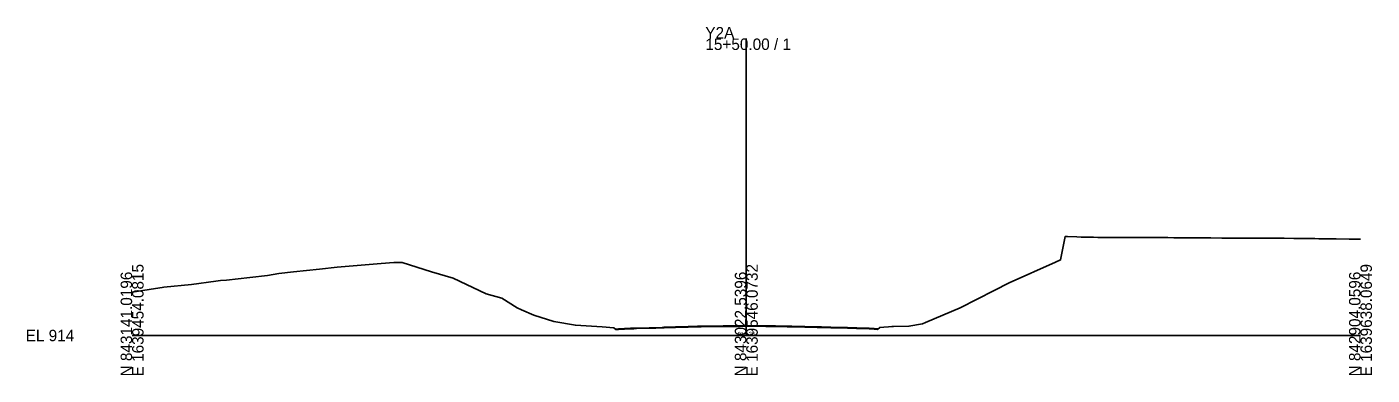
# Model space of a CAD drawing. Extents: x -26 to 303, y -10 to 10517.
# Drawn here: x -25.7 to 302.8, y 4990.3 to 5075.5 of the extents above; entities that cross this region are included whole.
import ezdxf

# ---------------------------------------------------------------- set-up
doc = ezdxf.new("R2010")
doc.units = 0
for name, color, linetype in [('Exist Cross Section Cell', 7, 'Continuous'), ('Exist XS Center Line Elevation Label', 7, 'Continuous'), ('Exist XS Ground Line', 7, 'Continuous'), ('Prop CMT Pvmt Surface Overlay', 7, 'Continuous')]:
    doc.layers.add(name, color=color, linetype=linetype)

msp = doc.modelspace()

# ---------------------------------------------------------------- linework, layer by layer
at = {"layer": 'Exist Cross Section Cell'}
for p, q in [((150, 5000), (150, 5072.63)), ((0, 5000), (150, 5000)), ((150, 5000), (300, 5000))]:
    msp.add_line(p, q, dxfattribs=at)
at = {"layer": 'Exist XS Ground Line'}
msp.add_lwpolyline([(0, 5010.63), (6.79, 5011.64), (7.34, 5011.73), (7.77, 5011.78), (14.47, 5012.51), (20.43, 5013.25), (21.59, 5013.42), (23.09, 5013.55), (28.72, 5014.2), (33.09, 5014.71), (35.85, 5015.15), (39.4, 5015.54), (45.75, 5016.25), (50.1, 5016.74), (60.79, 5017.57), (63.96, 5017.86), (65.96, 5017.88), (73.15, 5015.56), (78.38, 5014.05), (86.47, 5010.22), (90.28, 5009.13), (94.04, 5006.77), (95.07, 5006.28), (98.15, 5005), (103.02, 5003.45), (108.26, 5002.5), (114.77, 5002.08), (117.67, 5001.91), (118.12, 5001.43), (118.77, 5001.47), (120.25, 5001.56), (121.75, 5001.63), (122.54, 5001.66), (123.15, 5001.68), (126.31, 5001.78), (127.88, 5001.82), (129.48, 5001.87), (129.91, 5001.88), (131.64, 5001.93), (132.69, 5001.96), (133.98, 5002.01), (135.81, 5002.07), (136.79, 5002.1), (138.06, 5002.13), (138.57, 5002.14), (138.97, 5002.14), (142.14, 5002.19), (143.1, 5002.19), (144.34, 5002.21), (145.3, 5002.22), (146.02, 5002.23), (147.13, 5002.23), (147.48, 5002.24), (148.47, 5002.24), (149.26, 5002.25), (150.29, 5002.26), (151.05, 5002.27), (151.63, 5002.27), (154.8, 5002.24), (155.26, 5002.23), (157.14, 5002.2), (158.03, 5002.19), (158.44, 5002.18), (159.95, 5002.15), (161.13, 5002.13), (162.52, 5002.09), (164.29, 5002.05), (166.59, 5002), (167.31, 5001.98), (168.36, 5001.95), (169.91, 5001.92), (170.67, 5001.9), (173.79, 5001.84), (174.75, 5001.81), (175.99, 5001.76), (176.95, 5001.74), (178.82, 5001.7), (180, 5001.66), (181.2, 5001.56), (182.01, 5001.5), (182.64, 5001.98), (183.58, 5002.04), (184.7, 5002.12), (185.51, 5002.18), (185.98, 5002.19), (189.7, 5002.28), (193.07, 5002.87), (193.73, 5003.15), (202.23, 5006.79), (210.5, 5010.98), (214.2, 5012.85), (225.49, 5017.91), (226.76, 5018.49), (227.17, 5020.53), (227.9, 5024.21), (228.41, 5024.19), (230.76, 5024.1), (231.82, 5024.08), (233.92, 5024.04), (234.83, 5024.01), (235.89, 5024), (237.09, 5023.97), (237.71, 5023.96), (239.2, 5023.98), (239.91, 5023.99), (240.3, 5023.99), (241.92, 5023.99), (243.42, 5023.99), (244.05, 5023.99), (245.48, 5023.98), (246.59, 5023.97), (247.26, 5023.97), (248.12, 5023.96), (249.04, 5023.96), (249.75, 5023.96), (250.82, 5023.95), (252.2, 5023.94), (252.6, 5023.94), (252.92, 5023.93), (254.38, 5023.92), (256.28, 5023.91), (257.95, 5023.89), (259.25, 5023.88), (259.73, 5023.87), (260.35, 5023.87), (262.41, 5023.86), (263.44, 5023.86), (266.12, 5023.84), (268.74, 5023.84), (270.42, 5023.83), (272.2, 5023.83), (272.58, 5023.82), (273.98, 5023.82), (275.07, 5023.81), (275.76, 5023.8), (276.66, 5023.8), (277.55, 5023.8), (278.24, 5023.8), (279.33, 5023.78), (280.73, 5023.77), (281.4, 5023.77), (283.72, 5023.73), (284.81, 5023.72), (286.46, 5023.72), (287.73, 5023.71), (288.06, 5023.71), (288.88, 5023.7), (289.82, 5023.68), (290.64, 5023.68), (291.28, 5023.67), (292.05, 5023.66), (292.74, 5023.66), (294.06, 5023.64), (297.23, 5023.59), (298.93, 5023.58), (300, 5023.56)], dxfattribs=at)
at = {"layer": 'Prop CMT Pvmt Surface Overlay'}
msp.add_lwpolyline([(118.01, 5001.55), (118.76, 5001.59), (120.25, 5001.68), (121.75, 5001.76), (122.53, 5001.79), (123.14, 5001.81), (126.31, 5001.9), (129.47, 5001.99), (129.9, 5002), (131.64, 5002.06), (132.69, 5002.09), (133.98, 5002.13), (135.8, 5002.2), (136.79, 5002.23), (138.06, 5002.25), (138.57, 5002.26), (138.97, 5002.27), (142.14, 5002.31), (143.1, 5002.32), (144.34, 5002.33), (145.3, 5002.34), (146.02, 5002.35), (147.13, 5002.35), (147.47, 5002.36), (148.47, 5002.37), (149.26, 5002.37), (150.29, 5002.39), (151.04, 5002.4), (151.63, 5002.39), (154.8, 5002.36), (155.26, 5002.35), (157.15, 5002.33), (158.03, 5002.31), (158.44, 5002.3), (159.96, 5002.28), (161.13, 5002.25), (164.3, 5002.17), (166.6, 5002.12), (167.32, 5002.11), (168.36, 5002.08), (170.67, 5002.03), (173.79, 5001.96), (174.75, 5001.93), (175.99, 5001.89), (176.96, 5001.87), (178.83, 5001.82), (180.01, 5001.79), (181.21, 5001.69), (182.16, 5001.62)], dxfattribs=at)

# ---------------------------------------------------------------- texts
at = {"layer": 'Exist Cross Section Cell'}
for s, p in [('Y2A', (140, 5072.63)), ('15+50.00 / 1', (140, 5069.83)), ('EL 914', (-26, 4998.6))]:
    msp.add_text(s, height=2.8, dxfattribs=at).set_placement(p)
for s, p in [('E 1639454.0815', (2.8, 4990)), ('E 1639546.0732', (152.8, 4990)), ('E 1639638.0649', (302.8, 4990)), ('N 843141.0196', (0, 4990)), ('N 843022.5396', (150, 4990)), ('N 842904.0596', (300, 4990))]:
    msp.add_text(s, height=2.8, rotation=90, dxfattribs=at).set_placement(p)
at = {"layer": 'Exist XS Center Line Elevation Label'}
msp.add_text('916.26', height=1, dxfattribs=at).set_placement((147.9, 4999.89))

doc.saveas('drawing.dxf')
